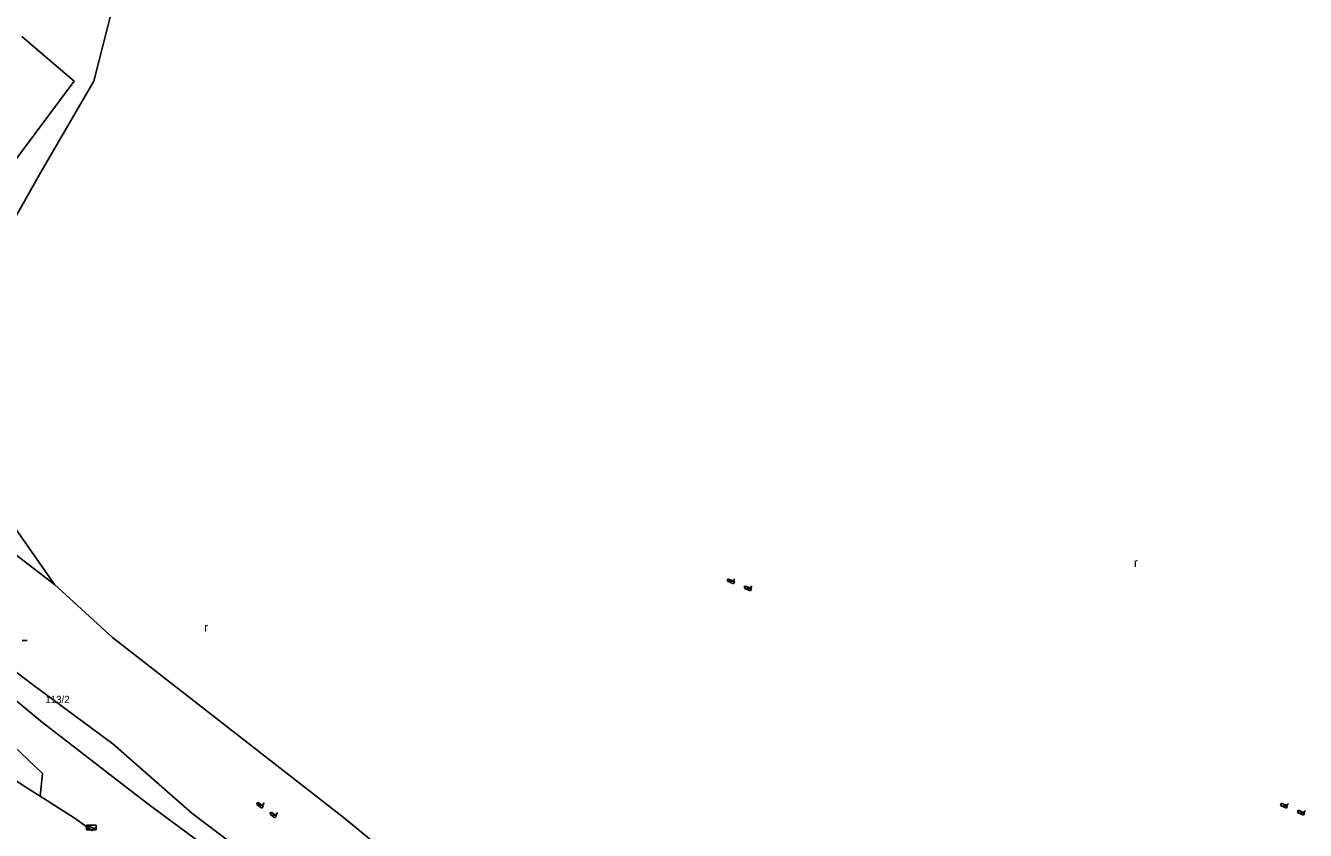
# Model space of a CAD drawing. Extents: x -836739 to -835945, y -1070775 to -1070126.
# Drawn here: x -836458 to -836326.2, y -1070365.3 to -1070282.5 of the extents above; entities that cross this region are included whole.
import ezdxf

# ---------------------------------------------------------------- set-up
doc = ezdxf.new("R2010")
doc.units = 0
for name, color, linetype in [('BodPole_mer', 7, 'Continuous'), ('Doprava_hranice', 7, 'Continuous'), ('OstPloch_hranice', 7, 'Continuous'), ('OstPloch_kody', 7, 'Continuous'), ('PovrZnIS_body', 7, 'Continuous'), ('PovrZnIS_hranice', 7, 'Continuous'), ('PovrZnIS_kody', 7, 'Continuous'), ('RuianPar_popis', 7, 'Continuous'), ('Stavby_linie', 7, 'Continuous')]:
    doc.layers.add(name, color=color, linetype=linetype)

msp = doc.modelspace()

# ---------------------------------------------------------------- linework, layer by layer
at = {"layer": 'BodPole_mer'}
for p, q in [((-836452.98, -1070288.18), (-836452.98, -1070288.18)), ((-836450.95, -1070288.2), (-836450.95, -1070288.2)), ((-836456.41, -1070297.54), (-836456.41, -1070297.54)), ((-836455, -1070340), (-836455, -1070340)), ((-836385.68, -1070339.66), (-836385.68, -1070339.66)), ((-836385.68, -1070339.66), (-836385.68, -1070339.66)), ((-836385.59, -1070339.43), (-836385.59, -1070339.43)), ((-836385.59, -1070339.43), (-836385.59, -1070339.43)), ((-836385.07, -1070339.91), (-836385.07, -1070339.91)), ((-836385.07, -1070339.91), (-836385.07, -1070339.91)), ((-836384.98, -1070339.68), (-836384.98, -1070339.68)), ((-836384.98, -1070339.68), (-836384.98, -1070339.68)), ((-836383.84, -1070340.17), (-836383.84, -1070340.17)), ((-836383.84, -1070340.17), (-836383.84, -1070340.17)), ((-836383.93, -1070340.4), (-836383.93, -1070340.4)), ((-836383.93, -1070340.4), (-836383.93, -1070340.4)), ((-836383.32, -1070340.65), (-836383.32, -1070340.65)), ((-836383.32, -1070340.65), (-836383.32, -1070340.65)), ((-836383.23, -1070340.42), (-836383.23, -1070340.42)), ((-836383.23, -1070340.42), (-836383.23, -1070340.42)), ((-836449.03, -1070345.44), (-836449.03, -1070345.44)), ((-836457.27, -1070350.28), (-836457.27, -1070350.28)), ((-836456.25, -1070354.2), (-836456.25, -1070354.2)), ((-836449.01, -1070356.39), (-836449.01, -1070356.39)), ((-836456.25, -1070359.46), (-836456.25, -1070359.46)), ((-836457.94, -1070360.84), (-836457.94, -1070360.84)), ((-836457.94, -1070360.84), (-836457.94, -1070360.84)), ((-836456.49, -1070361.78), (-836456.49, -1070361.78)), ((-836445.54, -1070362.45), (-836445.54, -1070362.45)), ((-836434.16, -1070362.62), (-836434.16, -1070362.62)), ((-836434.16, -1070362.62), (-836434.16, -1070362.62)), ((-836434.01, -1070362.42), (-836434.01, -1070362.42)), ((-836434.01, -1070362.42), (-836434.01, -1070362.42)), ((-836328.63, -1070362.51), (-836328.63, -1070362.51)), ((-836328.63, -1070362.51), (-836328.63, -1070362.51)), ((-836440.87, -1070363.54), (-836440.87, -1070363.54)), ((-836433.66, -1070363.01), (-836433.66, -1070363.01)), ((-836433.66, -1070363.01), (-836433.66, -1070363.01)), ((-836433.5, -1070362.81), (-836433.5, -1070362.81)), ((-836433.5, -1070362.81), (-836433.5, -1070362.81)), ((-836432.8, -1070363.63), (-836432.8, -1070363.63)), ((-836432.8, -1070363.63), (-836432.8, -1070363.63)), ((-836432.64, -1070363.44), (-836432.64, -1070363.44)), ((-836432.64, -1070363.44), (-836432.64, -1070363.44)), ((-836432.15, -1070363.82), (-836432.15, -1070363.82)), ((-836432.15, -1070363.82), (-836432.15, -1070363.82)), ((-836425.28, -1070363.93), (-836425.28, -1070363.93)), ((-836328.73, -1070362.74), (-836328.73, -1070362.74)), ((-836328.73, -1070362.74), (-836328.73, -1070362.74)), ((-836328.13, -1070363), (-836328.13, -1070363)), ((-836328.13, -1070363), (-836328.13, -1070363)), ((-836328.03, -1070362.77), (-836328.03, -1070362.77)), ((-836328.03, -1070362.77), (-836328.03, -1070362.77)), ((-836326.98, -1070363.46), (-836326.98, -1070363.46)), ((-836326.98, -1070363.46), (-836326.98, -1070363.46)), ((-836326.87, -1070363.23), (-836326.87, -1070363.23)), ((-836326.87, -1070363.23), (-836326.87, -1070363.23)), ((-836326.37, -1070363.75), (-836326.37, -1070363.75)), ((-836326.37, -1070363.75), (-836326.37, -1070363.75)), ((-836326.26, -1070363.52), (-836326.26, -1070363.52)), ((-836326.26, -1070363.52), (-836326.26, -1070363.52)), ((-836452.99, -1070364.02), (-836452.99, -1070364.02)), ((-836451.22, -1070365), (-836451.22, -1070365)), ((-836451.22, -1070365), (-836451.22, -1070365)), ((-836432.3, -1070364.02), (-836432.3, -1070364.02)), ((-836432.3, -1070364.02), (-836432.3, -1070364.02))]:
    msp.add_line(p, q, dxfattribs=at)
at = {"layer": 'Doprava_hranice'}
for points in [[(-836496.52, -1070319.54), (-836488.05, -1070326.94), (-836479.74, -1070333.71), (-836473.51, -1070339.57), (-836464.27, -1070347.56), (-836456.25, -1070354.2), (-836445.54, -1070362.45), (-836432.86, -1070371.82), (-836421.65, -1070379.55), (-836415.3, -1070382.95)], [(-836490.91, -1070321.78), (-836479.74, -1070331.15), (-836472.55, -1070338.03), (-836463.6, -1070345.51), (-836457.27, -1070350.28), (-836449.01, -1070356.39), (-836440.87, -1070363.54), (-836429.17, -1070372.36), (-836419.16, -1070378.17), (-836410.31, -1070384.67), (-836403.72, -1070387.61), (-836401.28, -1070388.23), (-836398.49, -1070390.5), (-836396.2, -1070392.51)], [(-836456.49, -1070361.78), (-836456.25, -1070359.46), (-836459.92, -1070355.96), (-836465.33, -1070351.01), (-836472.65, -1070344.35), (-836480.74, -1070337.07), (-836490.99, -1070328.59), (-836496.17, -1070324.43), (-836496.72, -1070324.41), (-836497.13, -1070324.67), (-836498.53, -1070327.13), (-836499.22, -1070328.53), (-836500.71, -1070331.34), (-836502.21, -1070333.5), (-836505.09, -1070337.45), (-836506.09, -1070338.88), (-836509.04, -1070344.01), (-836513.54, -1070341.59), (-836515.98, -1070341.87)]]:
    msp.add_lwpolyline(points, dxfattribs=at)
at = {"layer": 'OstPloch_hranice'}
for points in [[(-836356.62, -1070406.87), (-836370.19, -1070399.44), (-836385.43, -1070392.2), (-836396.38, -1070386.03), (-836404.41, -1070381.11), (-836409.87, -1070376.61), (-836425.28, -1070363.93), (-836449.03, -1070345.44), (-836455, -1070340), (-836462.64, -1070329.11), (-836464.81, -1070325.47), (-836465.74, -1070321.03), (-836464.89, -1070314.87), (-836461.62, -1070306.74), (-836456.41, -1070297.54), (-836450.95, -1070288.2), (-836447.03, -1070272.79), (-836441.38, -1070260.76)], [(-836455, -1070340), (-836466.66, -1070331.05), (-836473.91, -1070325.6), (-836480.18, -1070324.33)]]:
    msp.add_lwpolyline(points, dxfattribs=at)
at = {"layer": 'OstPloch_kody'}
msp.add_line((-836458.33, -1070345.75), (-836457.83, -1070345.75), dxfattribs=at)
at = {"layer": 'PovrZnIS_body'}
for p, q in [((-836451.72, -1070365.25), (-836451.72, -1070364.75)), ((-836451.72, -1070364.75), (-836450.72, -1070364.75)), ((-836451.72, -1070365.25), (-836451.72, -1070364.75)), ((-836451.72, -1070364.75), (-836450.72, -1070364.75)), ((-836450.72, -1070365.25), (-836451.72, -1070365.25)), ((-836450.72, -1070365.25), (-836451.72, -1070365.25)), ((-836451.64, -1070365.08), (-836451.53, -1070365.08)), ((-836451.64, -1070365.08), (-836451.53, -1070365.08)), ((-836451.53, -1070365.08), (-836451.53, -1070364.83)), ((-836451.53, -1070364.83), (-836451.03, -1070365.08)), ((-836451.53, -1070365.08), (-836451.53, -1070364.83)), ((-836451.53, -1070364.83), (-836451.03, -1070365.08)), ((-836451.03, -1070365.08), (-836450.79, -1070365.08)), ((-836451.03, -1070365.08), (-836450.79, -1070365.08)), ((-836450.72, -1070364.75), (-836450.72, -1070365.25)), ((-836450.72, -1070364.75), (-836450.72, -1070365.25))]:
    msp.add_line(p, q, dxfattribs=at)
at = {"layer": 'PovrZnIS_hranice'}
for p, q in [((-836385.68, -1070339.66), (-836385.07, -1070339.91)), ((-836385.68, -1070339.66), (-836385.07, -1070339.91)), ((-836383.93, -1070340.4), (-836383.32, -1070340.65)), ((-836383.93, -1070340.4), (-836383.32, -1070340.65)), ((-836434.16, -1070362.62), (-836433.66, -1070363.01)), ((-836434.16, -1070362.62), (-836433.66, -1070363.01)), ((-836432.8, -1070363.63), (-836432.3, -1070364.02)), ((-836432.8, -1070363.63), (-836432.3, -1070364.02)), ((-836328.73, -1070362.74), (-836328.13, -1070363)), ((-836328.73, -1070362.74), (-836328.13, -1070363)), ((-836326.98, -1070363.46), (-836326.37, -1070363.75)), ((-836326.98, -1070363.46), (-836326.37, -1070363.75))]:
    msp.add_line(p, q, dxfattribs=at)
for points in [[(-836385.68, -1070339.66), (-836385.59, -1070339.43), (-836384.98, -1070339.68), (-836385.07, -1070339.91)], [(-836385.68, -1070339.66), (-836385.59, -1070339.43), (-836384.98, -1070339.68), (-836385.07, -1070339.91)], [(-836383.93, -1070340.4), (-836383.84, -1070340.17), (-836383.23, -1070340.42), (-836383.32, -1070340.65)], [(-836383.93, -1070340.4), (-836383.84, -1070340.17), (-836383.23, -1070340.42), (-836383.32, -1070340.65)], [(-836434.16, -1070362.62), (-836434.01, -1070362.42), (-836433.5, -1070362.81), (-836433.66, -1070363.01)], [(-836434.16, -1070362.62), (-836434.01, -1070362.42), (-836433.5, -1070362.81), (-836433.66, -1070363.01)], [(-836328.73, -1070362.74), (-836328.63, -1070362.51), (-836328.03, -1070362.77), (-836328.13, -1070363)], [(-836328.73, -1070362.74), (-836328.63, -1070362.51), (-836328.03, -1070362.77), (-836328.13, -1070363)], [(-836432.8, -1070363.63), (-836432.64, -1070363.44), (-836432.15, -1070363.82), (-836432.3, -1070364.02)], [(-836432.8, -1070363.63), (-836432.64, -1070363.44), (-836432.15, -1070363.82), (-836432.3, -1070364.02)], [(-836326.98, -1070363.46), (-836326.87, -1070363.23), (-836326.26, -1070363.52), (-836326.37, -1070363.75)], [(-836326.98, -1070363.46), (-836326.87, -1070363.23), (-836326.26, -1070363.52), (-836326.37, -1070363.75)]]:
    msp.add_lwpolyline(points, dxfattribs=at)
at = {"layer": 'PovrZnIS_kody'}
for p, q in [((-836385.77, -1070339.46), (-836385.65, -1070339.46)), ((-836385.77, -1070339.46), (-836385.65, -1070339.46)), ((-836385.65, -1070339.46), (-836385.65, -1070339.66)), ((-836385.65, -1070339.46), (-836385.65, -1070339.66)), ((-836385.65, -1070339.66), (-836385.05, -1070339.66)), ((-836385.65, -1070339.66), (-836385.05, -1070339.66)), ((-836385.05, -1070339.66), (-836385.05, -1070339.46)), ((-836385.05, -1070339.46), (-836384.92, -1070339.46)), ((-836385.05, -1070339.66), (-836385.05, -1070339.46)), ((-836385.05, -1070339.46), (-836384.92, -1070339.46)), ((-836384, -1070340.2), (-836383.88, -1070340.2)), ((-836384, -1070340.2), (-836383.88, -1070340.2)), ((-836383.88, -1070340.2), (-836383.88, -1070340.4)), ((-836383.88, -1070340.2), (-836383.88, -1070340.4)), ((-836383.28, -1070340.4), (-836383.28, -1070340.2)), ((-836383.28, -1070340.2), (-836383.15, -1070340.2)), ((-836383.28, -1070340.4), (-836383.28, -1070340.2)), ((-836383.28, -1070340.2), (-836383.15, -1070340.2)), ((-836383.88, -1070340.4), (-836383.28, -1070340.4)), ((-836383.88, -1070340.4), (-836383.28, -1070340.4)), ((-836434.22, -1070362.52), (-836434.1, -1070362.52)), ((-836434.22, -1070362.52), (-836434.1, -1070362.52)), ((-836434.1, -1070362.52), (-836434.1, -1070362.72)), ((-836434.1, -1070362.52), (-836434.1, -1070362.72)), ((-836433.5, -1070362.72), (-836433.5, -1070362.52)), ((-836433.5, -1070362.52), (-836433.37, -1070362.52)), ((-836433.5, -1070362.72), (-836433.5, -1070362.52)), ((-836433.5, -1070362.52), (-836433.37, -1070362.52)), ((-836328.77, -1070362.6), (-836328.65, -1070362.6)), ((-836328.77, -1070362.6), (-836328.65, -1070362.6)), ((-836328.65, -1070362.6), (-836328.65, -1070362.8)), ((-836328.65, -1070362.6), (-836328.65, -1070362.8)), ((-836328.05, -1070362.8), (-836328.05, -1070362.6)), ((-836328.05, -1070362.6), (-836327.92, -1070362.6)), ((-836328.05, -1070362.8), (-836328.05, -1070362.6)), ((-836328.05, -1070362.6), (-836327.92, -1070362.6)), ((-836434.1, -1070362.72), (-836433.5, -1070362.72)), ((-836434.1, -1070362.72), (-836433.5, -1070362.72)), ((-836432.85, -1070363.54), (-836432.73, -1070363.54)), ((-836432.85, -1070363.54), (-836432.73, -1070363.54)), ((-836432.73, -1070363.54), (-836432.73, -1070363.74)), ((-836432.73, -1070363.54), (-836432.73, -1070363.74)), ((-836432.73, -1070363.74), (-836432.13, -1070363.74)), ((-836432.73, -1070363.74), (-836432.13, -1070363.74)), ((-836432.13, -1070363.74), (-836432.13, -1070363.54)), ((-836432.13, -1070363.54), (-836432, -1070363.54)), ((-836432.13, -1070363.74), (-836432.13, -1070363.54)), ((-836432.13, -1070363.54), (-836432, -1070363.54)), ((-836328.65, -1070362.8), (-836328.05, -1070362.8)), ((-836328.65, -1070362.8), (-836328.05, -1070362.8)), ((-836327.02, -1070363.32), (-836326.9, -1070363.32)), ((-836327.02, -1070363.32), (-836326.9, -1070363.32)), ((-836326.9, -1070363.32), (-836326.9, -1070363.52)), ((-836326.9, -1070363.32), (-836326.9, -1070363.52)), ((-836326.9, -1070363.52), (-836326.3, -1070363.52)), ((-836326.9, -1070363.52), (-836326.3, -1070363.52)), ((-836326.3, -1070363.52), (-836326.3, -1070363.32)), ((-836326.3, -1070363.32), (-836326.17, -1070363.32)), ((-836326.3, -1070363.52), (-836326.3, -1070363.32)), ((-836326.3, -1070363.32), (-836326.17, -1070363.32))]:
    msp.add_line(p, q, dxfattribs=at)
at = {"layer": 'RuianPar_popis'}
msp.add_line((-836455.95, -1070352.2), (-836455.95, -1070352.2), dxfattribs=at)
at = {"layer": 'Stavby_linie'}
for p, q in [((-836457.94, -1070360.84), (-836456.49, -1070361.78)), ((-836457.94, -1070360.84), (-836456.49, -1070361.78)), ((-836456.49, -1070361.78), (-836452.99, -1070364.02)), ((-836452.99, -1070364.02), (-836451.09, -1070365.35))]:
    msp.add_line(p, q, dxfattribs=at)
for points in [[(-836483.95, -1070318.68), (-836480.18, -1070324.33), (-836477.38, -1070322.05), (-836462.13, -1070300.43), (-836452.98, -1070288.18), (-836458.36, -1070283.6)], [(-836457.94, -1070360.84), (-836463.18, -1070357.45), (-836463.65, -1070357.11), (-836464.69, -1070356.37)]]:
    msp.add_lwpolyline(points, dxfattribs=at)

# ---------------------------------------------------------------- texts
at = {"layer": 'OstPloch_kody'}
for p in [(-836343.82, -1070338.18), (-836439.59, -1070344.86)]:
    msp.add_text('r', height=0.9, dxfattribs=at).set_placement(p)
at = {"layer": 'RuianPar_popis'}
msp.add_text('113/2', height=0.75, dxfattribs=at).set_placement((-836455.95, -1070352.2))

doc.saveas('drawing.dxf')
